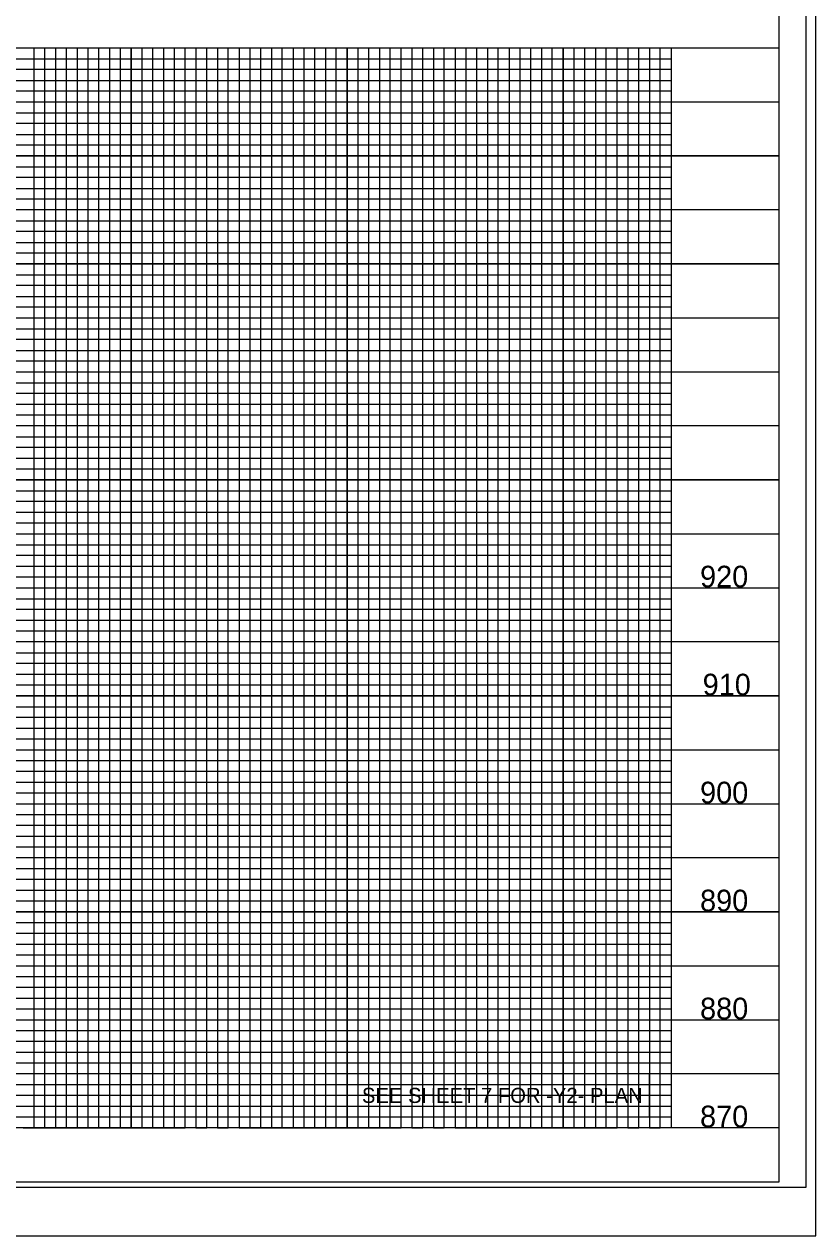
# Model space of a CAD drawing. Extents: x 1650661 to 1652901, y 832691 to 833791.
# Drawn here: x 1652355 to 1652721, y 832691 to 833252 of the extents above; entities that cross this region are included whole.
import ezdxf

# ---------------------------------------------------------------- set-up
doc = ezdxf.new("R2010")
doc.units = 0
for name, color, linetype in [('Exist Vertical Profile Vertical Axis Label', 7, 'Continuous'), ('Prop Dimension', 7, 'Continuous'), ('Prop Grid Mask', 7, 'Continuous'), ('Sheet Cutting Line CELL', 7, 'Continuous'), ('Sheet DOT Grid CELL', 7, 'Continuous'), ('Sheet Layout Profile Border Port 2', 7, 'Continuous'), ('Sheet Plot Border Inside CELL', 7, 'Continuous'), ('Sheet Plot Border Outside CELL', 7, 'Continuous'), ('Sheet Profile CELL', 7, 'Continuous'), ('Sheet Profile Grid Major CELL', 7, 'Continuous'), ('Sheet Profile Grid Middle CELL', 7, 'Continuous'), ('Sheet Profile Grid Minor CELL', 7, 'Continuous')]:
    doc.layers.add(name, color=color, linetype=linetype)

msp = doc.modelspace()

# ---------------------------------------------------------------- linework, layer by layer
at = {"layer": 'Prop Grid Mask'}
msp.add_lwpolyline([(1652509.28, 832766.02), (1652509.28, 832746.02), (1652644.28, 832746.02), (1652644.28, 832766.02)], close=True, dxfattribs=at)
at = {"layer": 'Sheet Cutting Line CELL'}
msp.add_line((1651037.28, 832691.02), (1652721.28, 832691.02), dxfattribs=at)
at = {"layer": 'Sheet DOT Grid CELL'}
for p, q in [((1651204.28, 833241.02), (1652704.17, 833241.02)), ((1652404.28, 833241.02), (1652404.28, 832741.02)), ((1652454.28, 833241.02), (1652454.28, 832741.02)), ((1652504.28, 833241.02), (1652504.28, 832741.02)), ((1652554.28, 833241.02), (1652554.28, 832741.02)), ((1652604.28, 833241.02), (1652604.28, 832741.02)), ((1652654.28, 833241.02), (1652654.28, 832741.02)), ((1651204.28, 833191.02), (1652704.17, 833191.02)), ((1651204.28, 833141.02), (1652704.17, 833141.02)), ((1651204.28, 833091.02), (1652704.17, 833091.02)), ((1651204.28, 833041.02), (1652704.17, 833041.02)), ((1651204.28, 832991.02), (1652704.17, 832991.02)), ((1651204.28, 832941.02), (1652704.17, 832941.02)), ((1651204.28, 832891.02), (1652704.17, 832891.02)), ((1651204.28, 832841.02), (1652704.17, 832841.02)), ((1651204.28, 832791.02), (1652704.17, 832791.02))]:
    msp.add_line(p, q, dxfattribs=at)
at = {"layer": 'Sheet Layout Profile Border Port 2'}
msp.add_lwpolyline([(1651254.28, 833241.02), (1652654.28, 833241.02), (1652654.28, 832741.02), (1651254.28, 832741.02)], close=True, dxfattribs=at)
at = {"layer": 'Sheet Plot Border Inside CELL'}
msp.add_lwpolyline([(1651050.28, 832713.47), (1652716.78, 832713.47), (1652716.78, 833768.57), (1651050.28, 833768.57)], close=True, dxfattribs=at)
at = {"layer": 'Sheet Plot Border Outside CELL'}
msp.add_lwpolyline([(1651037.28, 832691.02), (1652721.28, 832691.02), (1652721.28, 833791.02), (1651037.28, 833791.02)], close=True, dxfattribs=at)
at = {"layer": 'Sheet Profile CELL'}
for p, q in [((1651204.28, 833241.02), (1652704.28, 833241.02)), ((1652704.28, 832741.02), (1651204.28, 832741.02)), ((1651204.28, 832716.02), (1652704.28, 832716.02))]:
    msp.add_line(p, q, dxfattribs=at)
msp.add_lwpolyline([(1652704.28, 833766.02), (1651204.28, 833766.02), (1651204.28, 832716.02), (1652704.28, 832716.02)], close=True, dxfattribs=at)
at = {"layer": 'Sheet Profile Grid Major CELL'}
for p, q in [((1652404.28, 833241.02), (1652454.28, 833241.02)), ((1652504.28, 833241.02), (1652554.28, 833241.02)), ((1652604.28, 833241.02), (1652654.28, 833241.02)), ((1652604.28, 832741.02), (1652604.28, 832741.02))]:
    msp.add_line(p, q, dxfattribs=at)
for points in [[(1652354.28, 832741.02), (1652404.28, 832741.02), (1652404.28, 833241.02), (1652454.28, 833241.02), (1652454.28, 832741.02), (1652504.28, 832741.02), (1652504.28, 833241.02), (1652554.28, 833241.02), (1652554.28, 832741.02), (1652604.28, 832741.02), (1652604.28, 832741.02), (1652604.28, 833241.02), (1652654.28, 833241.02), (1652654.28, 832741.02)], [(1652704.28, 833191.02), (1651204.28, 833191.02)], [(1652704.28, 833141.02), (1651204.28, 833141.02), (1651204.28, 833091.02), (1652704.28, 833091.02)], [(1652704.28, 833041.02), (1651204.28, 833041.02), (1651204.28, 832991.02), (1652704.28, 832991.02)], [(1652704.28, 832941.02), (1651204.28, 832941.02), (1651204.28, 832891.02), (1652704.28, 832891.02)], [(1652704.28, 832841.02), (1651204.28, 832841.02), (1651204.28, 832841.02), (1651204.28, 832791.02), (1652704.28, 832791.02)], [(1652704.28, 832741.02), (1651204.28, 832741.02)]]:
    msp.add_lwpolyline(points, dxfattribs=at)
at = {"layer": 'Sheet Profile Grid Middle CELL'}
for points in [[(1652329.28, 833241.02), (1652379.28, 833241.02), (1652379.28, 832741.02), (1652429.28, 832741.02), (1652429.28, 833241.02), (1652479.28, 833241.02), (1652479.28, 832741.02), (1652529.28, 832741.02), (1652529.28, 833241.02), (1652579.28, 833241.02), (1652579.28, 832741.02), (1652629.28, 832741.02), (1652629.28, 833241.02)], [(1651204.28, 833216.02), (1652704.28, 833216.02)], [(1652704.28, 833166.02), (1651204.28, 833166.02), (1651204.28, 833116.02), (1652704.28, 833116.02)], [(1652704.28, 833066.02), (1651204.28, 833066.02), (1651204.28, 833016.02), (1652704.28, 833016.02)], [(1652704.28, 832966.02), (1651204.28, 832966.02), (1651204.28, 832916.02), (1652704.28, 832916.02)], [(1652704.28, 832866.02), (1651204.28, 832866.02), (1651204.28, 832816.02), (1652704.28, 832816.02)], [(1652704.28, 832766.02), (1651204.28, 832766.02)]]:
    msp.add_lwpolyline(points, dxfattribs=at)
at = {"layer": 'Sheet Profile Grid Minor CELL'}
for p, q in [((1651254.28, 833236.02), (1652654.28, 833236.02)), ((1652654.28, 833231.02), (1651254.28, 833231.02)), ((1651254.28, 833226.02), (1652654.28, 833226.02)), ((1652654.28, 833221.02), (1651254.28, 833221.02)), ((1651254.28, 833211.02), (1652654.28, 833211.02)), ((1652654.28, 833206.02), (1651254.28, 833206.02)), ((1651254.28, 833201.02), (1652654.28, 833201.02)), ((1652654.28, 833196.02), (1651254.28, 833196.02)), ((1651254.28, 833186.02), (1652654.28, 833186.02)), ((1652654.28, 833181.02), (1651254.28, 833181.02)), ((1651254.28, 833176.02), (1652654.28, 833176.02)), ((1652654.28, 833171.02), (1651254.28, 833171.02)), ((1651254.28, 833161.02), (1652654.28, 833161.02)), ((1652654.28, 833156.02), (1651254.28, 833156.02)), ((1651254.28, 833151.02), (1652654.28, 833151.02)), ((1652654.28, 833146.02), (1651254.28, 833146.02)), ((1651254.28, 833136.02), (1652654.28, 833136.02)), ((1652654.28, 833131.02), (1651254.28, 833131.02)), ((1651254.28, 833126.02), (1652654.28, 833126.02)), ((1652654.28, 833121.02), (1651254.28, 833121.02)), ((1651254.28, 833111.02), (1652654.28, 833111.02)), ((1652654.28, 833106.02), (1651254.28, 833106.02)), ((1651254.28, 833101.02), (1652654.28, 833101.02)), ((1652654.28, 833096.02), (1651254.28, 833096.02)), ((1651254.28, 833086.02), (1652654.28, 833086.02)), ((1652654.28, 833081.02), (1651254.28, 833081.02)), ((1651254.28, 833076.02), (1652654.28, 833076.02)), ((1652654.28, 833071.02), (1651254.28, 833071.02)), ((1651254.28, 833061.02), (1652654.28, 833061.02)), ((1652654.28, 833056.02), (1651254.28, 833056.02)), ((1651254.28, 833051.02), (1652654.28, 833051.02)), ((1652654.28, 833046.02), (1651254.28, 833046.17)), ((1651254.28, 833036.02), (1652654.28, 833036.02)), ((1652654.28, 833031.02), (1651254.28, 833031.02)), ((1651254.28, 833026.02), (1652654.28, 833026.02)), ((1652654.28, 833021.02), (1651254.28, 833021.02)), ((1651254.28, 833011.02), (1652654.28, 833011.02)), ((1652654.28, 833006.02), (1651254.28, 833006.02)), ((1651254.28, 833001.02), (1652654.28, 833001.02)), ((1652654.28, 832996.02), (1651254.28, 832996.02)), ((1651254.28, 832986.02), (1652654.28, 832986.02)), ((1652654.28, 832981.02), (1651254.28, 832981.02)), ((1651254.28, 832976.02), (1652654.28, 832976.02)), ((1652654.28, 832971.02), (1651254.28, 832971.02)), ((1651254.28, 832961.02), (1652654.28, 832961.02)), ((1652654.28, 832956.02), (1651254.28, 832956.02)), ((1651254.28, 832951.02), (1652654.28, 832951.02)), ((1652654.28, 832946.02), (1651254.28, 832946.02)), ((1651254.28, 832936.02), (1652654.28, 832936.02)), ((1652654.28, 832931.02), (1651254.28, 832931.02)), ((1651254.28, 832926.02), (1652654.28, 832926.02)), ((1652654.28, 832921.02), (1651254.28, 832921.02)), ((1651254.28, 832911.02), (1652654.28, 832911.02)), ((1652654.28, 832906.02), (1651254.28, 832906.02)), ((1651254.28, 832901.02), (1652654.28, 832901.02)), ((1652654.28, 832896.02), (1651254.28, 832896.02)), ((1651254.28, 832886.02), (1652654.28, 832886.02)), ((1652654.28, 832881.02), (1651254.28, 832881.02)), ((1651254.28, 832876.02), (1652654.28, 832876.02)), ((1652654.28, 832871.02), (1651254.28, 832871.02)), ((1651254.28, 832861.02), (1652654.28, 832861.02)), ((1652654.28, 832856.02), (1651254.28, 832856.02)), ((1651254.28, 832851.02), (1652654.28, 832851.02)), ((1652654.28, 832846.02), (1651254.28, 832846.02)), ((1651254.28, 832836.02), (1652654.28, 832836.02)), ((1652654.28, 832831.02), (1651254.28, 832831.02)), ((1651254.28, 832826.02), (1652654.28, 832826.02)), ((1652654.28, 832821.02), (1651254.28, 832821.02)), ((1651254.28, 832811.02), (1652654.28, 832811.02)), ((1652654.28, 832806.02), (1651254.28, 832806.02)), ((1651254.28, 832801.02), (1652654.28, 832801.02)), ((1652654.28, 832796.02), (1651254.28, 832796.02)), ((1651254.28, 832786.02), (1652654.28, 832786.02)), ((1652654.28, 832781.02), (1651254.28, 832781.02)), ((1651254.28, 832776.02), (1652654.28, 832776.02)), ((1652654.28, 832771.02), (1651254.28, 832771.02)), ((1651254.28, 832761.02), (1652654.28, 832761.02)), ((1652654.28, 832756.02), (1651254.28, 832756.02)), ((1651254.28, 832751.02), (1652654.28, 832751.02)), ((1651254.28, 832746.02), (1652654.28, 832746.02)), ((1652654.28, 832746.02), (1652654.28, 832746.02))]:
    msp.add_line(p, q, dxfattribs=at)
for points in [[(1652349.28, 833241.02), (1652359.28, 833241.02), (1652359.28, 832741.02), (1652364.28, 832741.02), (1652364.28, 833241.02), (1652369.28, 833241.02), (1652369.28, 832741.02), (1652374.28, 832741.02), (1652374.28, 833241.02), (1652384.28, 833241.02), (1652384.28, 832741.02), (1652389.28, 832741.02), (1652389.28, 833241.02), (1652394.28, 833241.02), (1652394.28, 832741.02)], [(1652394.28, 832741.02), (1652399.28, 832741.02), (1652399.28, 833241.02), (1652409.28, 833241.02), (1652409.28, 832741.02), (1652414.28, 832741.02), (1652414.28, 833241.02), (1652419.28, 833241.02), (1652419.28, 832741.02), (1652424.28, 832741.02), (1652424.28, 833241.02), (1652434.28, 833241.02), (1652434.28, 832741.02), (1652439.28, 832741.02), (1652439.28, 833241.02), (1652444.28, 833241.02), (1652444.28, 832741.02), (1652449.28, 832741.02), (1652449.28, 833241.02), (1652459.28, 833241.02), (1652459.28, 832741.02), (1652464.28, 832741.02), (1652464.28, 833241.02), (1652469.28, 833241.02), (1652469.28, 832741.02), (1652474.28, 832741.02), (1652474.28, 833241.02), (1652484.28, 833241.02), (1652484.28, 832741.02), (1652489.28, 832741.02), (1652489.28, 833241.02), (1652494.28, 833241.02), (1652494.28, 832741.02), (1652499.28, 832741.02), (1652499.28, 833241.02), (1652509.28, 833241.02), (1652509.28, 832741.02), (1652514.28, 832741.02), (1652514.28, 833241.02), (1652519.28, 833241.02), (1652519.28, 832741.02), (1652524.28, 832741.02), (1652524.28, 833241.02), (1652534.28, 833241.02), (1652534.28, 832741.02), (1652539.28, 832741.02), (1652539.28, 833241.02), (1652544.28, 833241.02), (1652544.28, 832741.02), (1652549.28, 832741.02), (1652549.28, 833241.02), (1652559.28, 833241.02), (1652559.28, 832741.02), (1652564.28, 832741.02), (1652564.28, 833241.02), (1652569.28, 833241.02), (1652569.28, 832741.02), (1652574.28, 832741.02), (1652574.28, 833241.02), (1652584.28, 833241.02), (1652584.28, 832741.02), (1652589.28, 832741.02), (1652589.28, 833241.02), (1652594.28, 833241.02), (1652594.28, 832741.02), (1652599.28, 832741.02), (1652599.28, 833241.02), (1652609.28, 833241.02), (1652609.28, 832741.02), (1652614.28, 832741.02), (1652614.28, 833241.02), (1652619.28, 833241.02), (1652619.28, 832741.02), (1652624.28, 832741.02), (1652624.28, 833241.02), (1652634.28, 833241.02), (1652634.28, 832741.02), (1652639.28, 832741.02), (1652639.28, 833241.02), (1652644.28, 833241.02), (1652644.28, 832741.02), (1652649.28, 832741.02), (1652649.28, 833241.02), (1652654.28, 833241.02)]]:
    msp.add_lwpolyline(points, dxfattribs=at)

# ---------------------------------------------------------------- texts
at = {"layer": 'Exist Vertical Profile Vertical Axis Label'}
for s, p in [('920', (1652667.71, 832991.27)), ('910', (1652668.91, 832941.27)), ('900', (1652667.71, 832891.27)), ('890', (1652667.71, 832841.27)), ('880', (1652667.71, 832791.27)), ('870', (1652667.71, 832741.27))]:
    msp.add_text(s, height=10, dxfattribs=at).set_placement(p)
at = {"layer": 'Prop Dimension'}
msp.add_text('SEE SHEET 7 FOR -Y2- PLAN', height=7, dxfattribs=at).set_placement((1652511.14, 832752.52))

doc.saveas('drawing.dxf')
